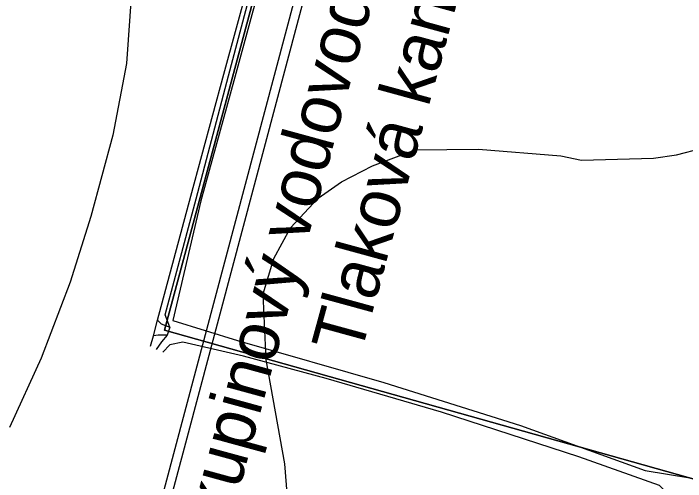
# Model space of a CAD drawing. Extents: x -555887 to -552101, y -1100251 to -1096546.
# Drawn here: x -554095.1 to -553897.5, y -1098736.4 to -1098598.8 of the extents above; entities that cross this region are included whole.
import ezdxf

# ---------------------------------------------------------------- set-up
doc = ezdxf.new("R2010")
doc.units = 0
for name, color, linetype in [('07_KANALIZACE', 7, 'Continuous'), ('07_VODOVOD', 7, 'Continuous'), ('vrstevnice', 7, 'Continuous'), ('ZSST', 7, 'Continuous'), ('zájem', 7, 'Continuous')]:
    doc.layers.add(name, color=color, linetype=linetype)

msp = doc.modelspace()

# ---------------------------------------------------------------- linework, layer by layer
at = {"layer": '07_KANALIZACE'}
msp.add_lwpolyline([(-554087.21, -1098884.94), (-554044.09, -1098723.55), (-553946.28, -1098356.13), (-553945.28, -1098350.61), (-553945.11, -1098348.21), (-553937.04, -1098317.66), (-553932.95, -1098309.77), (-553933.89, -1098299.13), (-553960.89, -1098094.71)], dxfattribs=at)
at = {"layer": '07_VODOVOD'}
msp.add_lwpolyline([(-554079.66, -1098847.14), (-553997.7, -1098539.18), (-553945.85, -1098344.3), (-553938.25, -1098317.52), (-553935.78, -1098308.01), (-553936.18, -1098296.39), (-554003.21, -1097797.26)], dxfattribs=at)
at = {"layer": 'vrstevnice'}
for points in [[(-554116.19, -1098536.46), (-554094.99, -1098535.76), (-554083.89, -1098537.86), (-554076.31, -1098541.66), (-554069.71, -1098548.11), (-554064.66, -1098556.54), (-554060.59, -1098568.9), (-554059.46, -1098578.44), (-554059.88, -1098591.36), (-554060.44, -1098592.63), (-554061.85, -1098613.55), (-554065.92, -1098634.61), (-554072.38, -1098658.48), (-554078.42, -1098677.86), (-554086.98, -1098700.18), (-554096.25, -1098720.54)], [(-554014.11, -1098747.22), (-554015.37, -1098731.22), (-554020.85, -1098700.61), (-554021.73, -1098681.22), (-554018.6, -1098670.84), (-554013.69, -1098661.85), (-554005.54, -1098653.15), (-553998.66, -1098648.37), (-553989.54, -1098643.6), (-553977.04, -1098638.96), (-553958.36, -1098638.68), (-553934.21, -1098640.65), (-553928.17, -1098641.91), (-553906.97, -1098641.35), (-553900.23, -1098640.37), (-553885.07, -1098636.44), (-553866.77, -1098629.28)]]:
    msp.add_lwpolyline(points, dxfattribs=at)
at = {"layer": 'ZSST'}
for points in [[(-554054.81, -1098696.59), (-554053.95, -1098693.56), (-554052.78, -1098689.01), (-554042.99, -1098652.55), (-554033.29, -1098616.71), (-554022.44, -1098576.81), (-554007.03, -1098518.73), (-553997.47, -1098483.19), (-553987.92, -1098447.16), (-553980.78, -1098420.44), (-553979.49, -1098415.59), (-553977.44, -1098407.81), (-553973.16, -1098391.31), (-553969.69, -1098378.4), (-553965.21, -1098361.58), (-553960.59, -1098344.24)], [(-554049.19, -1098691), (-554050.52, -1098687.46), (-554041.41, -1098653.36), (-554031.87, -1098617.14), (-554021.28, -1098577.24), (-554005.55, -1098519.29), (-553995.62, -1098484.1), (-553986.23, -1098447.46), (-553979.26, -1098420.2)], [(-553976.46, -1098420.59), (-553982.14, -1098443.13), (-553993.59, -1098484.91), (-554003.65, -1098520), (-554019.29, -1098577.95), (-554030.05, -1098617.61), (-554040, -1098653.89), (-554048.29, -1098689.04)], [(-554052.78, -1098689.01), (-554051.7, -1098690.03), (-554049.19, -1098691), (-554049.92, -1098693.37), (-554052.54, -1098693.36), (-554053.95, -1098693.56)], [(-554048.29, -1098689.04), (-554029.24, -1098694.91), (-553986.21, -1098707.34), (-553946.06, -1098719.92), (-553909.4, -1098733.2), (-553896.32, -1098735.34)], [(-554049.92, -1098693.37), (-554051.64, -1098695.32), (-554053.19, -1098697.63)], [(-553900.09, -1098742.67), (-553905.22, -1098737.61), (-553928.92, -1098729.13), (-553969.26, -1098715.99), (-554003.17, -1098706.15), (-554027.46, -1098699.56), (-554045.32, -1098695.47), (-554049.11, -1098696.22), (-554051.22, -1098698.39)]]:
    msp.add_lwpolyline(points, dxfattribs=at)
at = {"layer": 'zájem'}
for points in [[(-553979.24, -1098426.19), (-554050.69, -1098691.93), (-553893.64, -1098736.07), (-553884.75, -1098731.38), (-553882.48, -1098724.24), (-553874.02, -1098698.09), (-553864.7, -1098667.88), (-553857.14, -1098643.4), (-553819.71, -1098517.47), (-553816.99, -1098366.76)], [(-553816.99, -1098366.76), (-553819.71, -1098517.47), (-553857.14, -1098643.4), (-553864.7, -1098667.88), (-553874.02, -1098698.09), (-553882.48, -1098724.24), (-553884.75, -1098731.38), (-553893.64, -1098736.07), (-554050.69, -1098691.93), (-553979.24, -1098426.19)]]:
    msp.add_lwpolyline(points, dxfattribs=at)

# ---------------------------------------------------------------- texts
at = {"layer": '07_KANALIZACE'}
msp.add_text('Tlaková kanalizace', height=15, rotation=74.7137, dxfattribs=at).set_placement((-553993.15, -1098699.81))
at = {"layer": '07_VODOVOD'}
msp.add_text('skupinový vodovod SOMU - sever', height=15, rotation=74.7137, dxfattribs=at).set_placement((-554034.02, -1098758.24))

doc.saveas('drawing.dxf')
